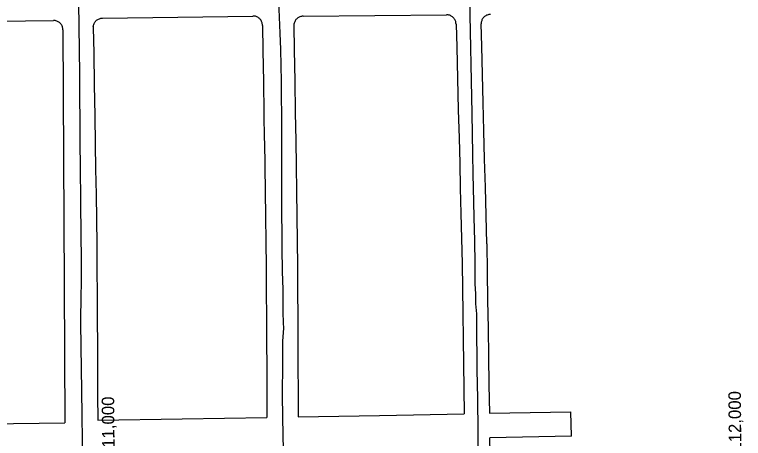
# Model space of a CAD drawing. Extents: x -2233 to 187241, y 4582 to 150524.
# Drawn here: x 110831 to 111994, y 60147 to 60823 of the extents above; entities that cross this region are included whole.
import ezdxf

# ---------------------------------------------------------------- set-up
doc = ezdxf.new("R2010")
doc.units = 0
for name, color, linetype in [('GE_X_CL_2000', 7, 'Continuous'), ('GRID', 7, 'Continuous'), ('RW_X_Fee_RW', 7, 'Continuous')]:
    doc.layers.add(name, color=color, linetype=linetype)

msp = doc.modelspace()

# ---------------------------------------------------------------- linework, layer by layer
at = {"layer": 'GE_X_CL_2000'}
for points in [[(110932.6, 60841.8), (110933.4, 60804.1), (110934, 60766.3), (110934.3, 60728.6), (110934.3, 60690.8), (110934.6, 60654.1), (110934.9, 60617.5), (110935.2, 60580.8), (110935.9, 60524.8), (110936.5, 60471), (110937, 60434.4), (110937.1, 60414.6), (110937, 60394.7), (110936.7, 60374.9), (110935.8, 60334.8), (110935.9, 60331.5), (110936.5, 60293.7), (110936.8, 60258.1), (110937.3, 60223.7), (110939, 60104.7)], [(111252, 60844.6), (111253.1, 60818.9), (111254.1, 60793.2), (111254.9, 60767.6), (111255.6, 60741.9), (111256, 60716.2), (111256.3, 60690.6), (111256.4, 60664.9), (111256.4, 60612.4), (111256.6, 60524.8), (111257.1, 60454.8), (111257.6, 60409.9), (111258.1, 60402.8), (111258.5, 60395.6), (111258.7, 60388.5), (111258.8, 60381.3), (111258.6, 60374.1), (111258.7, 60361.4), (111258.9, 60348.6), (111259.3, 60331.5), (111259.6, 60323), (111258.5, 60302.4), (111258.2, 60273.5), (111258, 60265.9), (111257.7, 60217.8), (111258.1, 60180.2), (111259.3, 60127.9)], [(111556.6, 60848.5), (111560.6, 60665.2), (111560.8, 60632.9), (111561.2, 60600.7), (111561.9, 60568.4), (111563.1, 60524.8), (111563.8, 60499.4), (111564.6, 60462.5), (111565, 60425.6), (111565.1, 60409.7), (111565.4, 60393.7), (111566, 60377.8), (111566, 60361.9), (111567.9, 60346), (111568, 60331.5), (111568.2, 60256.8), (111569.3, 60211.1), (111569.9, 60158.2), (111570.6, 60103)]]:
    msp.add_lwpolyline(points, dxfattribs=at)
at = {"layer": 'RW_X_Fee_RW'}
for p, q in [((110778.1, 60812.5), (110892.8, 60813.6)), ((111588.3, 60187.7), (111718.3, 60189.6)), ((111719.2, 60150.7), (111718.3, 60189.6)), ((111719.2, 60150.7), (111589.2, 60148.5))]:
    msp.add_line(p, q, dxfattribs=at)
for points in [[(110956.4, 60803.7), (110956.5, 60805), (110956.8, 60806.2), (110957.2, 60807.5), (110957.7, 60808.7), (110958.3, 60809.9), (110959, 60811), (110959.7, 60812), (110960.6, 60813), (110961.6, 60813.9), (110962.6, 60814.7), (110963.7, 60815.4), (110964.9, 60816), (110966.1, 60816.5), (110967.3, 60816.9), (110968.6, 60817.2), (110969.9, 60817.4), (110971.2, 60817.4)], [(110971.2, 60817.4), (111091, 60819.1), (111211.1, 60820.8)], [(111226.3, 60805.9), (111226.2, 60807.2), (111226, 60808.5), (111225.8, 60809.7), (111225.4, 60811), (111224.8, 60812.2), (111224.2, 60813.4), (111223.5, 60814.5), (111222.7, 60815.5), (111221.8, 60816.5), (111220.8, 60817.3), (111219.8, 60818.1), (111218.7, 60818.8), (111217.5, 60819.4), (111216.3, 60819.9), (111215, 60820.3), (111213.8, 60820.6), (111212.5, 60820.7), (111211.1, 60820.8)], [(111291.2, 60820.5), (111289.9, 60820.4), (111288.6, 60820.2), (111287.3, 60819.9), (111286.1, 60819.5), (111284.8, 60819), (111283.7, 60818.4), (111282.6, 60817.7), (111281.6, 60816.9), (111280.6, 60816), (111279.7, 60815), (111279, 60814), (111278.3, 60812.9), (111277.7, 60811.7), (111277.2, 60810.5), (111276.8, 60809.2), (111276.5, 60808), (111276.4, 60806.7), (111276.3, 60805.4)], [(111291.2, 60820.5), (111405.6, 60821.6), (111520.1, 60822.7)], [(111535.2, 60807.9), (111535.1, 60809.2), (111534.9, 60810.5), (111534.6, 60811.8), (111534.2, 60813), (111533.7, 60814.2), (111533.1, 60815.4), (111532.4, 60816.5), (111531.6, 60817.5), (111530.7, 60818.4), (111529.7, 60819.3), (111528.7, 60820.1), (111527.6, 60820.8), (111526.4, 60821.4), (111525.2, 60821.9), (111523.9, 60822.2), (111522.7, 60822.5), (111521.4, 60822.7), (111520.1, 60822.7)], [(111590.1, 60823.4), (111588.7, 60823.3), (111587.4, 60823.2), (111586.2, 60822.9), (111584.9, 60822.4), (111583.7, 60821.9), (111582.6, 60821.3), (111581.5, 60820.6), (111580.4, 60819.8), (111579.5, 60818.9), (111578.6, 60817.9), (111577.8, 60816.8), (111577.1, 60815.7), (111576.5, 60814.6), (111576.1, 60813.3), (111575.7, 60812.1), (111575.4, 60810.8), (111575.3, 60809.5), (111575.2, 60808.2)], [(110908, 60798.7), (110907.9, 60800), (110907.7, 60801.3), (110907.4, 60802.6), (110907, 60803.8), (110906.5, 60805), (110905.9, 60806.2), (110905.2, 60807.3), (110904.4, 60808.3), (110903.5, 60809.3), (110902.5, 60810.2), (110901.5, 60811), (110900.3, 60811.7), (110899.2, 60812.3), (110898, 60812.8), (110896.7, 60813.1), (110895.4, 60813.4), (110894.1, 60813.6), (110892.8, 60813.6)], [(110956.4, 60803.7), (110956.3, 60802.4), (110957, 60761.3), (110957.9, 60711.3), (110958.7, 60661.4), (110959.4, 60616.4), (110960, 60576.4), (110960.7, 60536.4), (110961.3, 60496.4), (110962, 60456.4)], [(111226.3, 60805.9), (111226.9, 60765.9), (111227.7, 60715.9), (111228.5, 60665.9), (111229.2, 60623.4), (111229.3, 60620.9), (111229.9, 60580.9), (111230.6, 60540.9), (111231.2, 60501), (111231.9, 60460.9)], [(111276.3, 60805.4), (111276.9, 60766.7), (111277.7, 60716.7), (111278.5, 60666.7), (111279.3, 60621.7), (111279.9, 60581.7), (111280.5, 60541.7), (111281.2, 60501.7), (111281.9, 60461.8)], [(111535.2, 60807.9), (111536.2, 60771.1), (111537.5, 60721.2), (111538.8, 60671.2), (111539.9, 60626.2), (111541, 60586.2), (111542, 60546.2), (111543, 60506.2), (111544.1, 60466.2)], [(111584.3, 60457.7), (111583.1, 60502.7), (111582, 60547.7), (111580.8, 60592.6), (111579.6, 60637.6), (111578.5, 60682.6), (111577.3, 60727.6), (111576.1, 60772.6), (111575.2, 60808.2)], [(110908, 60798.7), (110910, 60392.4), (110911.1, 60172.4)], [(111544.1, 60466.2), (111544.8, 60426.3), (111545.4, 60386.3), (111546, 60346.3), (111546.5, 60306.3), (111547.1, 60266.3), (111547.7, 60226.3), (111548.3, 60186.3)], [(110962, 60456.4), (110962.2, 60416.4), (110962.4, 60376.4), (110962.6, 60336.4), (110962.8, 60296.4), (110963, 60256.4), (110963.2, 60216.4), (110963.4, 60176.4)], [(111231.9, 60460.9), (111232.1, 60420.9), (111232.4, 60380.9), (111232.6, 60340.9), (111232.8, 60300.9), (111233, 60260.9), (111233.2, 60220.9), (111233.4, 60180.9)], [(111281.9, 60461.8), (111282.1, 60421.8), (111282.3, 60381.8), (111282.5, 60341.8), (111282.7, 60301.8), (111282.9, 60261.8), (111283.1, 60221.8), (111283.3, 60181.8)], [(111584.3, 60457.7), (111585, 60412.7), (111585.6, 60367.7), (111586.3, 60322.7), (111587, 60277.7), (111587.6, 60232.7), (111588.3, 60187.7)], [(111283.3, 60181.8), (111413.3, 60184), (111548.3, 60186.3)], [(110963.4, 60176.4), (111098.4, 60178.7), (111233.4, 60180.9)], [(110652.6, 60168.1), (110787.6, 60170.4), (110911.1, 60172.4)], [(111603, 59562.6), (111600.3, 59678.6), (111599.1, 59728.6), (111598.1, 59773.6), (111597, 59818.6), (111596, 59863.5), (111594.9, 59908.5), (111593.8, 59953.5), (111592.8, 59998.5), (111591.6, 60048.5), (111590.4, 60098.5), (111589.2, 60148.5)]]:
    msp.add_lwpolyline(points, dxfattribs=at)

# ---------------------------------------------------------------- texts
at = {"layer": 'GRID'}
for s, p in [('E 112,000', (111990.7, 60101)), ('E 111,000', (110990.7, 60092.3))]:
    msp.add_text(s, height=20, rotation=90.5, dxfattribs=at).set_placement(p)

doc.saveas('drawing.dxf')
